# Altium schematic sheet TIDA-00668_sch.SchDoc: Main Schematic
size 431 x 279 mm; Date: Not shown in title block; ApprovedBy: Not shown in title block; CheckedBy: Not shown in title block; Author: Not shown in title block; CompanyName: Not shown in title block; DrawnBy: Gordon Varney; Engineer: Gordon Varney; Organization: Not shown in title block; Address1: Not shown in title block; Address2: Not shown in title block; Address3: Not shown in title block; Address4: Not shown in title block; DocumentNumber: 1; Revision: Use project parameter SCH_Rev; SheetNumber: 2; SheetTotal: 3; PageSetup: Record=PageOptions¦CenterHorizontal=True¦CenterVertical=True¦PrintScale=0.64¦XCorrection=1.00¦YCorrection=1.00¦PrintKind=0¦BorderSize=5000000¦LeftOffset=0¦BottomOffset=0¦Orientation=2¦PaperLength=1000¦PaperWidth=1000¦Scale=100¦PaperSource=15¦PrintQuality=600¦MediaType=1¦DitherType=10¦PrintScaleMode=1¦PaperKind=Letter
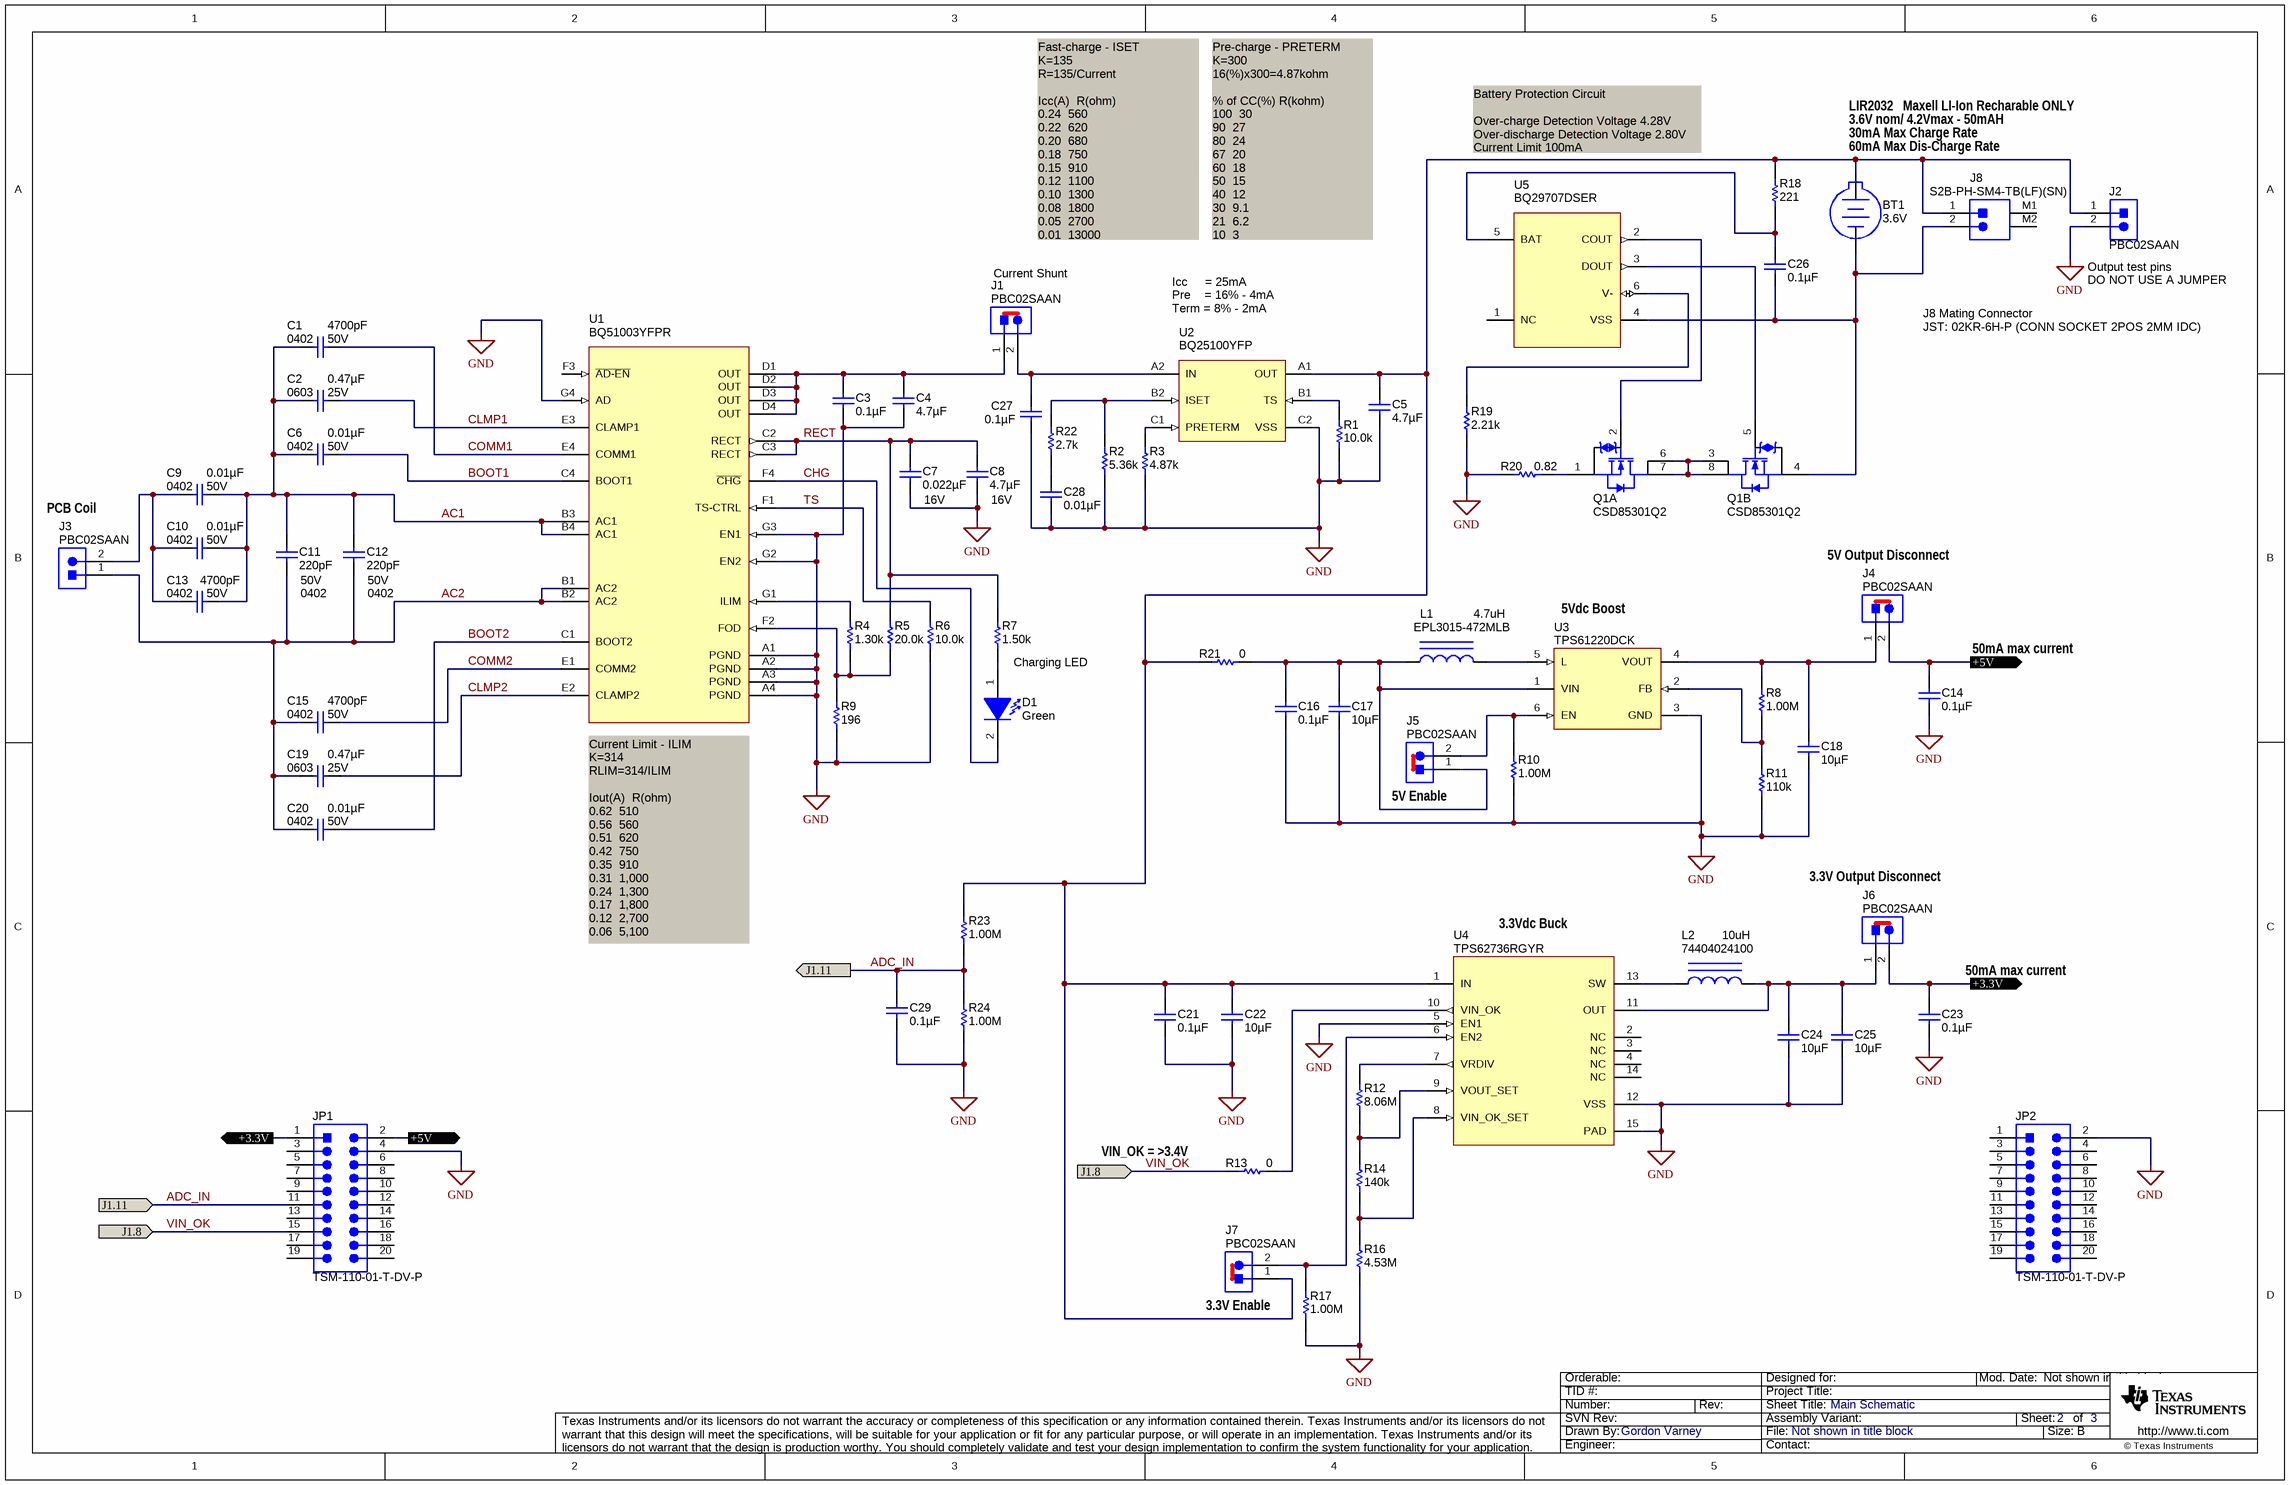
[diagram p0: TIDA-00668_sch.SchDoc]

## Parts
BT1  value 3.6V  [BAT_BS-7]  (hidden comment: BS-7)
C1  ValueDisplayed: 4700pF  Value2: 50V  [0402]  (hidden comment: C1005X8R1H472K)
C2  ValueDisplayed: 0.47µF  Value2: 25V  [0603]  (hidden comment: GRM188R71E474KA12D)
C3  ValueDisplayed: 0.1µF  [0402]  (hidden comment: GRM155R71A104KA01D)
C4  ValueDisplayed: 4.7µF  [0402]  (hidden comment: C1005X5R1A475K050BC)
C5  ValueDisplayed: 4.7µF  [0402]  (hidden comment: C1005X5R1A475K050BC)
C6  ValueDisplayed: 0.01µF  Value2: 50V  [0402]  (hidden comment: C0402C103J5RACTU)
C7  ValueDisplayed: 0.022µF  Value2: 16V  [0402]  (hidden comment: C1005X7R1C223K)
C8  ValueDisplayed: 4.7µF  Value2: 16V  [0603]  (hidden comment: GRM188R61C475KAAJ)
C9  ValueDisplayed: 0.01µF  Value2: 50V  [0402]  (hidden comment: C0402C103J5RACTU)
C10  ValueDisplayed: 0.01µF  Value2: 50V  [0402]  (hidden comment: C0402C103J5RACTU)
C11  ValueDisplayed: 220pF  Value2: 50V  [0402]  (hidden comment: GRM1555C1H221JA01D)
C12  ValueDisplayed: 220pF  Value2: 50V  [0402]  (hidden comment: GRM1555C1H221JA01D)
C13  ValueDisplayed: 4700pF  Value2: 50V  [0402]  (hidden comment: C1005X8R1H472K)
C14  ValueDisplayed: 0.1µF  [0402]  (hidden comment: GRM155R71A104KA01D)
C15  ValueDisplayed: 4700pF  Value2: 50V  [0402]  (hidden comment: C1005X8R1H472K)
C16  ValueDisplayed: 0.1µF  [0402]  (hidden comment: GRM155R71A104KA01D)
C17  ValueDisplayed: 10µF  [0603]  (hidden comment: C0603C106M9PACTU)
C18  ValueDisplayed: 10µF  [0603]  (hidden comment: C0603C106M9PACTU)
C19  ValueDisplayed: 0.47µF  Value2: 25V  [0603]  (hidden comment: GRM188R71E474KA12D)
C20  ValueDisplayed: 0.01µF  Value2: 50V  [0402]  (hidden comment: C0402C103J5RACTU)
C21  ValueDisplayed: 0.1µF  [0402]  (hidden comment: GRM155R71A104KA01D)
C22  ValueDisplayed: 10µF  [0603]  (hidden comment: C0603C106M9PACTU)
C23  ValueDisplayed: 0.1µF  [0402]  (hidden comment: GRM155R71A104KA01D)
C24  ValueDisplayed: 10µF  [0603]  (hidden comment: C0603C106M9PACTU)
C25  ValueDisplayed: 10µF  [0603]  (hidden comment: C0603C106M9PACTU)
C26  ValueDisplayed: 0.1µF  [0402]  (hidden comment: GRM155R71A104KA01D)
C27  ValueDisplayed: 0.1µF  [0402]  (hidden comment: GRM155R71A104KA01D)
C28  ValueDisplayed: 0.01µF  [0402]  (hidden comment: C0402C103J5RACTU)
C29  ValueDisplayed: 0.1µF  [0402]  (hidden comment: GRM155R71A104KA01D)
D1  value Green  [LED_LTST-C190]  (hidden comment: LTST-C190GKT)
J1  PBC02SAAN  [Sullins_PBC02SAAN]
J2  PBC02SAAN  [Sullins_PBC02SAAN]
J3  PBC02SAAN  [Sullins_PBC02SAAN]
J4  PBC02SAAN  [Sullins_PBC02SAAN]
J5  PBC02SAAN  [Sullins_PBC02SAAN]
J6  PBC02SAAN  [Sullins_PBC02SAAN]
J7  PBC02SAAN  [Sullins_PBC02SAAN]
J8  S2B-PH-SM4-TB(LF)(SN)  [JST_S2B-PH-SM4-TB]
JP1  TSM-110-01-T-DV-P  [CONN_TSM-110-01-T-DV-P]
JP2  TSM-110-01-T-DV-P  [CONN_TSM-110-01-T-DV-P]
L1  EPL3015-472MLB  value 4.7uH  [EPL3015]
L2  74404024100  value 10uH  [WE_LQS_252012]
Q1  CSD85301Q2  [DQK0006B]  (parts A,B of 2)
R1  ValueDisplayed: 10.0k  [0402]  (hidden comment: CRCW040210K0FKED)
R2  ValueDisplayed: 5.36k  [0402]  (hidden comment: CRCW04025K36FKED)
R3  ValueDisplayed: 4.87k  [0402]  (hidden comment: CRCW04024K87FKED)
R4  ValueDisplayed: 1.30k  [0402]  (hidden comment: CRCW04021K30FKED)
R5  ValueDisplayed: 20.0k  [0402]  (hidden comment: CRCW040220K0FKED)
R6  ValueDisplayed: 10.0k  [0402]  (hidden comment: CRCW040210K0FKED)
R7  ValueDisplayed: 1.50k  [0402]  (hidden comment: CRCW04021K50FKED)
R8  ValueDisplayed: 1.00M  [0402]  (hidden comment: CRCW04021M00FKED)
R9  ValueDisplayed: 196  [0402]  (hidden comment: CRCW0402196RFKED)
R10  ValueDisplayed: 1.00M  [0402]  (hidden comment: CRCW04021M00FKED)
R11  ValueDisplayed: 110k  [0402]  (hidden comment: CRCW0402110KFKED)
R12  ValueDisplayed: 8.06M  [0402]  (hidden comment: CRCW04028M06FKED)
R13  ValueDisplayed: 0  [0402]  (hidden comment: CRCW04020000Z0ED)
R14  ValueDisplayed: 140k  [0402]  (hidden comment: CRCW0402140KFKED)
R16  ValueDisplayed: 4.53M  [0402]  (hidden comment: CRCW04024M53FKED)
R17  ValueDisplayed: 1.00M  [0402]  (hidden comment: CRCW04021M00FKED)
R18  ValueDisplayed: 221  [0402]  (hidden comment: CRCW0402221RFKED)
R19  ValueDisplayed: 2.21k  [0402]  (hidden comment: CRCW04022K21FKED)
R20  ValueDisplayed: 0.82  [0402]  (hidden comment: ERJ-2BQFR82X)
R21  ValueDisplayed: 0  [0402]  (hidden comment: CRCW04020000Z0ED)
R22  ValueDisplayed: 2.7k  [0402]  (hidden comment: CRCW04022K70JNED)
R23  ValueDisplayed: 1.00M  [0402]  (hidden comment: CRCW04021M00FKED)
R24  ValueDisplayed: 1.00M  [0402]  (hidden comment: CRCW04021M00FKED)
U1  BQ51003YFPR  [YFP0028APAL]
U2  BQ25100YFP  [YFP0006AFAV]
U3  TPS61220DCK  [DCK0006A_N]
U4  TPS62736RGYR  [RGY0014A]
U5  BQ29707DSER  [DSE0006A]

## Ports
+3.3V, +5V, J1.8, J1.11

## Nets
GND: C3.2 C4.2 C5.2 C7.2 C8.2 C14.2 C16.2 C17.2 C18.2 C21.2 C22.2 C23.2 C24.2 C25.2 C27.2 C28.2 C29.2 J2.2 JP1.4 JP2.2 R1.1 R2.1 R3.1 R6.1 R9.1 R10.1 R11.1 R16.1 R17.1 R19.1 R20.1 R24.1 U1.A1(PGND) U1.A2(PGND) U1.A3(PGND) U1.A4(PGND) U1.G2(EN2) U1.G3(EN1) U1.G4(AD) U2.C2(VSS) U3.3(GND) U4.5(EN1) U4.12(VSS) U4.15(PAD)
+3.3V: C23.1 J6.2 JP1.1 ; port +3.3V
+5V: C14.1 J4.2 JP1.2 ; port +5V
AC1: C1.2 C2.2 C6.2 C9.1 C10.1 C11.1 C12.1 C13.1 U1.B3(AC1) U1.B4(AC1)
AC2: C11.2 C12.2 C15.2 C19.2 C20.2 J3.1 U1.B1(AC2) U1.B2(AC2)
ADC_IN: C29.1 JP1.11 R23.1 R24.2 ; port J1.11
BOOT1: C6.1 U1.C4(BOOT1)
BOOT2: C20.1 U1.C1(BOOT2)
CHG: D1.2(K) U1.F4(~{CHG})
CLMP1: C2.1 U1.E3(CLAMP1)
CLMP2: C19.1 U1.E2(CLAMP2)
COMM1: C1.1 U1.E4(COMM1)
COMM2: C15.1 U1.E1(COMM2)
RECT: C7.1 C8.1 R5.2 R7.2 U1.C2(RECT) U1.C3(RECT)
TS: R6.2 U1.F1(TS-CTRL)
VIN_OK: JP1.15 R13.1 ; port J1.8
NetBT1_1: BT1.1(+) C5.1 C21.1 C22.1 J2.1 J7.1 J8.1 R18.2 R21.1 R23.2 U2.A1(OUT) U4.1(IN)
NetBT1_2: BT1.2(-) C26.2 J8.2 Q1.4(S2) U5.4(VSS)
NetC3_1: C3.1 C4.1 J1.1 U1.D1(OUT) U1.D2(OUT) U1.D3(OUT) U1.D4(OUT)
NetC9_2: C9.2 C10.2 C13.2 J3.2
NetC16_1: C16.1 C17.1 J5.1 L1.1 R21.2 U3.1(VIN)
NetC18_1: C18.1 J4.1 R8.2 U3.4(VOUT)
NetC24_1: C24.1 C25.1 J6.1 L2.2 U4.11(OUT)
NetC26_1: C26.1 R18.1 U5.5(BAT)
NetC27_1: C27.1 J1.2 U2.A2(IN)
NetC28_1: C28.1 R22.1
NetD1_1: D1.1(A) R7.1
NetJ5_2: J5.2 R10.2 U3.6(EN)
NetJ7_2: J7.2 R17.2 U4.6(EN2)
NetL1_2: L1.2 U3.5(L)
NetL2_1: L2.1 U4.13(SW)
NetQ1_1: Q1.1(S1) R20.2
NetQ1_2: Q1.2(G1) U5.2(COUT)
NetQ1_3: Q1.3(D2) Q1.6(D1) Q1.7(D1) Q1.8(D2)
NetQ1_5: Q1.5(G2) U5.3(DOUT)
NetR1_2: R1.2 U2.B1(TS)
NetR2_2: R2.2 R22.2 U2.B2(ISET)
NetR3_2: R3.2 U2.C1(PRETERM)
NetR4_1: R4.1 R5.1 R9.2 U1.F2(FOD)
NetR4_2: R4.2 U1.G1(ILIM)
NetR8_1: R8.1 R11.2 U3.2(FB)
NetR12_1: R12.1 R14.2 U4.9(VOUT_SET)
NetR12_2: R12.2 U4.7(VRDIV)
NetR13_2: R13.2 U4.10(VIN_OK)
NetR14_1: R14.1 R16.2 U4.8(VIN_OK_SET)
NetR19_2: R19.2 U5.6(V-)

Not connected (* = marked no-connect by the designer): J8 M1 M2; JP1 3 5 6 7 8 9 10 12 13 14 16 17 18 19 20; JP2 1 3 4 5 6 7 8 9 10 11 12 13 14 15 16 17 18 19 20; U1 F3(~{AD-EN}); U4 2(NC) 3(NC) 4(NC) 14(NC); U5 1(NC)

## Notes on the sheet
- Battery Protection Circuit
  Over-charge Detection Voltage 4.28V
  Over-discharge Detection Voltage 2.80V
  Current Limit 100mA
- 3.6V nom/ 4.2Vmax - 50mAH
- LIR2032
- 60mA Max Dis-Charge Rate
- 30mA Max Charge Rate
- Maxell LI-Ion Recharable ONLY
- Current Shunt
- Fast-charge - ISET
  K=135
  R=135/Current
  Icc(A)		R(ohm)
  0.24		560
  0.22		620
  0.20		680
  0.18		750
  0.15		910
  0.12		1100
  0.10		1300
  0.08		1800
  0.05		2700
  0.01		13000
- Pre-charge - PRETERM
  K=300
  16(%)x300=4.87kohm
  % of CC(%)	R(kohm)
  100		30
  90		27
  80		24
  67		20
  60		18
  50		15
  40		12
  30		9.1
  21		6.2
  10		3
- (near J2) Output test pins
- (near J2) DO NOT USE A JUMPER
- Icc     = 25mA
  Pre    = 16% - 4mA
  Term = 8% - 2mA
- J8 Mating Connector
- JST: 02KR-6H-P (CONN SOCKET 2POS 2MM IDC)
- (near J3) PCB Coil
- 5V Output Disconnect
- (near U3) 5Vdc Boost
- (near R7) Charging LED
- (near C14) 50mA max current
- (near J5) 5V Enable
- 3.3V Output Disconnect
- (near U1) Current Limit - ILIM
  K=314
  RLIM=314/ILIM
  Iout(A)		R(ohm)
  0.62		510
  0.56		560
  0.51		620
  0.42		750
  0.35		910
  0.31		1,000
  0.24		1,300
  0.17		1,800
  0.12		2,700
  0.06		5,100
- (near U4) 3.3Vdc Buck
- (near C23) 50mA max current
- (near R13) VIN_OK = >3.4V
- 3.3V Enable

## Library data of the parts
BT1 = BS-7: Battery Holder, CR2032, Retainer clip, TH; Manufacturer: Memory Protection Devices; SymbolCreator: a0412235
C1 C13 C15 = C1005X8R1H472K: CAP, CERM, 4700 pF, 50 V, +/- 10%, X8R, 0402; Manufacturer: TDK; Polarized: N; CompType: Capacitor; Value: 4700pF; U/M: EA; Cap_F: 0.0000000047; Tolerance_%: 10; ESR_ohm: 0.0899; Value1: 0.0899 ohm; VDC_V: 50; TaMin_C: -55; TaMax_C: 150; AEC Category: Q200
C2 C19 = GRM188R71E474KA12D: CAP, CERM, 0.47 µF, 25 V, +/- 10%, X7R, 0603; Manufacturer: MuRata; Polarized: N; CompType: Capacitor; Value: 0.47uF; U/M: EA; Cap_F: 0.00000047; Tolerance_%: 10; Value1: Unknown; VDC_V: 25; TaMin_C: -55; TaMax_C: 125
C3 C14 C16 C21 C23 C26 C27 C29 = GRM155R71A104KA01D: CAP, CERM, 0.1uF, 10V, +/-10%, X7R, 0402; Manufacturer: MuRata; Polarized: N; CompType: Capacitor; U/M: EA; Cap_F: 0.0000001; Tolerance_%: 10; Value1: Unknown; TaMin_C: -55; TaMax_C: 125
C4 C5 = C1005X5R1A475K050BC: CAP, CERM, 4.7 µF, 10 V, +/- 10%, X5R, 0402; Manufacturer: TDK; Polarized: N; CompType: Capacitor; Value: 4.7uF; U/M: EA; Cap_F: 0.0000047; Tolerance_%: 10; Value1: Unknown; Value2: 10V; TaMin_C: -55; TaMax_C: 85
C6 C20 = C0402C103J5RACTU: CAP, CERM, 0.01 µF, 50 V, +/- 5%, X7R, 0402; Manufacturer: Kemet; Polarized: N; CompType: Capacitor; Value: 0.01uF; U/M: EA; Cap_F: 0.00000001; Tolerance_%: 5; Value1: Unknown; VDC_V: 50; TaMin_C: -55; TaMax_C: 125
C7 = C1005X7R1C223K: CAP, CERM, 0.022 µF, 16 V, +/- 10%, X7R, 0402; Manufacturer: TDK; Polarized: N; CompType: Capacitor; Value: 0.022uF; U/M: EA; Cap_F: 0.000000022; Tolerance_%: 10; ESR_ohm: 0.0419; Value1: 0.0419 ohm; VDC_V: 16; TaMin_C: -55; TaMax_C: 125
C8 = GRM188R61C475KAAJ: CAP, CERM, 4.7 µF, 16 V, +/- 10%, X5R, 0603; Manufacturer: MuRata; Polarized: N; CompType: Capacitor; Value: 4.7uF; U/M: EA; Cap_F: 0.0000047; Tolerance_%: 10; Value1: Unknown; VDC_V: 16; TaMin_C: -55; TaMax_C: 85
C9 C10 = C0402C103J5RACTU: CAP, CERM, 0.01 µF, 50 V, +/- 5%, X7R, 0402; Manufacturer: Kemet; Polarized: N; CompType: Capacitor; Value: 0.01uF; U/M: EA; Cap_F: 0.00000001; Tolerance_%: 5; Value1: Unknown; VDC_V: 50; TaMin_C: -55; TaMax_C: 125; AEC Category: Q200
C11 C12 = GRM1555C1H221JA01D: CAP, CERM, 220 pF, 50 V, +/- 5%, C0G/NP0, 0402; Manufacturer: MuRata; Polarized: N; CompType: Capacitor; Value: 220pF; U/M: EA; Cap_F: 0.00000000022; Tolerance_%: 5; Value1: Unknown; VDC_V: 50; TaMin_C: -55; TaMax_C: 125; AEC Category: Q200
C17 C18 C22 C24 C25 = C0603C106M9PACTU: CAP, CERM, 10 µF, 6.3 V, +/- 20%, X5R, 0603; Manufacturer: Kemet; Polarized: N; CompType: Capacitor; Value: 10uF; U/M: EA; Cap_F: 0.00001; Tolerance_%: 20; ESR_ohm: 0.004; Value1: 0.004 ohm; VDC_V: 6.3; Value2: 6.3V; IRMS_A: 8.9; TaMin_C: -55; TaMax_C: 85
C28 = C0402C103J5RACTU: CAP, CERM, 0.01 µF, 50 V, +/- 5%, X7R, 0402; Manufacturer: Kemet; Polarized: N; CompType: Capacitor; Value: 0.01uF; U/M: EA; Cap_F: 0.00000001; Tolerance_%: 5; Value1: Unknown; VDC_V: 50; Value2: 50V; TaMin_C: -55; TaMax_C: 125
D1 = LTST-C190GKT: LED, Green, SMD; Manufacturer: Lite-On; Vf_V: 2.1; Value2: 2.1V; Io_A: 0.02; Power_TotalModule: 0.1; Value1: 0.1W; U/M: EA
J1-J7 = PBC02SAAN: Header, 100mil, 2x1, Gold, TH; Manufacturer: Sullins Connector Solutions; SymbolCreator: a0412235; U/M: EA
J8 = S2B-PH-SM4-TB(LF)(SN): Header (shrouded), 2mm, 2x1, R/A, SMT; Manufacturer: JST Manufacturing; SymbolCreator: x0208326; U/M: EA
JP1 JP2 = TSM-110-01-T-DV-P: Header, 100mil, 10x2, Tin, SMT; Manufacturer: Samtec; SymbolCreator: a0412235; U/M: EA
L1 = EPL3015-472MLB: Inductor, Shielded, Ferrite, 4.7 µH, 1.2 A, 0.14 ohm, SMD; Manufacturer: Coilcraft; Ind_H: 4.7E-6; ValueDisplayed: 4.7µH; Imax_A: 1.2; Irms: 1.4A @ 40C rise; Isat: 1.2A @ 30% inductance drop; DCR_ohm: 0.14; Value2: 1.2A
L2 = 74404024100: Inductor, Wirewound, Ferrite, 10 µH, 0.47 A, 0.435 ohm, SMD; Manufacturer: Wurth Elektronik eiSos; Ind_H: 10.0E-6; ValueDisplayed: 10µH; Imax_A: 0.47; Irms: 0.47A @ 40C rise; Isat: 0.85A @ 30% inductance drop; DCR_ohm: 0.435; Value2: 0.47A
Q1 = CSD85301Q2: MOSFET, N-CH, 20 V, 6.7 A, SMD, 2.0x2.0, Height 0.8mm; Manufacturer: Texas Instruments; Alternate Manufacturer: None; SymbolCreator: a0411947; U/M: EA; ChType: N; Value: 20V; VdsMax_V: 20; Value1: 0.023 ohm; Rdson45_ohm: 0.023; Value2: 4.2 nC; QgTyp_nC: 4.2; Vgs_V: 10; IdsMax_A: 6.7
R1 R6 = CRCW040210K0FKED: RES, 10.0 k, 1%, 0.063 W, 0402; Manufacturer: Vishay-Dale; CompType: Resistor; Value: 10.0k; Res_ohm: 10000; Value_Code: 10k0; Tolerance_%: 1; Power_W: 0.063; Value2: 0.063W; VDC_V: 50; TempCo: 100 ppm/C; EIA_Code: E96; U/M: EA
R2 = CRCW04025K36FKED: RES, 5.36 k, 1%, 0.063 W, 0402; Manufacturer: Vishay-Dale; CompType: Resistor; Value: 5.36k; Res_ohm: 5360; Value_Code: 5k36; Tolerance_%: 1; Power_W: 0.063; Value2: 0.063W; VDC_V: 50; TempCo: 100 ppm/C; EIA_Code: E96; U/M: EA
R3 = CRCW04024K87FKED: RES, 4.87 k, 1%, 0.063 W, 0402; Manufacturer: Vishay-Dale; CompType: Resistor; Value: 4.87k; Res_ohm: 4870; Value_Code: 4k87; Tolerance_%: 1; Power_W: 0.063; Value2: 0.063W; VDC_V: 50; TempCo: 100 ppm/C; EIA_Code: E96; U/M: EA
R4 = CRCW04021K30FKED: RES, 1.30 k, 1%, 0.063 W, 0402; Manufacturer: Vishay-Dale; CompType: Resistor; Value: 1.30k; Res_ohm: 1300; Value_Code: 1k30; Tolerance_%: 1; Power_W: 0.063; Value2: 0.063W; VDC_V: 50; TempCo: 100 ppm/C; EIA_Code: E96; U/M: EA
R5 = CRCW040220K0FKED: RES, 20.0 k, 1%, 0.063 W, 0402; Manufacturer: Vishay-Dale; CompType: Resistor; Value: 20.0k; Res_ohm: 20000; Value_Code: 20k0; Tolerance_%: 1; Power_W: 0.063; Value2: 0.063W; VDC_V: 50; TempCo: 100 ppm/C; EIA_Code: E96; U/M: EA
R7 = CRCW04021K50FKED: RES, 1.50 k, 1%, 0.063 W, 0402; Manufacturer: Vishay-Dale; CompType: Resistor; Value: 1.50k; Res_ohm: 1500; Value_Code: 1k50; Tolerance_%: 1; Power_W: 0.063; Value2: 0.063W; VDC_V: 50; TempCo: 100 ppm/C; EIA_Code: E96; U/M: EA
R8 R10 R17 R23 R24 = CRCW04021M00FKED: RES, 1.00 M, 1%, 0.063 W, 0402; Manufacturer: Vishay-Dale; CompType: Resistor; Value: 1.00Meg; Res_ohm: 1000000; Value_Code: 1M00; Tolerance_%: 1; Power_W: 0.063; Value2: 0.063W; VDC_V: 50; TempCo: 100 ppm/C; EIA_Code: E96; U/M: EA
R9 = CRCW0402196RFKED: RES, 196, 1%, 0.063 W, 0402; Manufacturer: Vishay-Dale; CompType: Resistor; Value: 196; Value_Code: 196R; Tolerance_%: 1; Power_W: 0.063; Value2: 0.063W; VDC_V: 50; TempCo: 100 ppm/C; EIA_Code: E96; U/M: EA
R11 = CRCW0402110KFKED: RES, 110 k, 1%, 0.063 W, 0402; Manufacturer: Vishay-Dale; CompType: Resistor; Value: 110k; Res_ohm: 110000; Tolerance_%: 1; Power_W: 0.063; Value2: 0.063W; VDC_V: 50; TempCo: 100 ppm/C; EIA_Code: E96; U/M: EA
R12 = CRCW04028M06FKED: RES, 8.06 M, 1%, 0.063 W, 0402; Manufacturer: Vishay-Dale; CompType: Resistor; Value: 8.06Meg; Res_ohm: 8060000; Value_Code: 8M06; Tolerance_%: 1; Power_W: 0.063; Value2: 0.063W; VDC_V: 50; TempCo: 100 ppm/C; EIA_Code: E96; U/M: EA
R13 R21 = CRCW04020000Z0ED: RES, 0, 5%, 0.063 W, 0402; Manufacturer: Vishay-Dale; CompType: Resistor; Value: 0; Value_Code: 0000; Tolerance_%: 5; Power_W: 0.063; Value2: 0.063W; VDC_V: 50; TempCo: 200 ppm/C; EIA_Code: E24; U/M: EA
R14 = CRCW0402140KFKED: RES, 140 k, 1%, 0.063 W, 0402; Manufacturer: Vishay-Dale; CompType: Resistor; Value: 140k; Res_ohm: 140000; Tolerance_%: 1; Power_W: 0.063; Value2: 0.063W; VDC_V: 50; TempCo: 100 ppm/C; EIA_Code: E96; U/M: EA
R16 = CRCW04024M53FKED: RES, 4.53 M, 1%, 0.063 W, 0402; Manufacturer: Vishay-Dale; CompType: Resistor; Value: 4.53Meg; Res_ohm: 4530000; Value_Code: 4M53; Tolerance_%: 1; Power_W: 0.063; Value2: 0.063W; VDC_V: 50; TempCo: 100 ppm/C; EIA_Code: E96; U/M: EA
R18 = CRCW0402221RFKED: RES, 221, 1%, 0.063 W, 0402; Manufacturer: Vishay-Dale; CompType: Resistor; Value: 221; Value_Code: 221R; Tolerance_%: 1; Power_W: 0.063; Value2: 0.063W; VDC_V: 50; TempCo: 100 ppm/C; EIA_Code: E96; U/M: EA
R19 = CRCW04022K21FKED: RES, 2.21 k, 1%, 0.063 W, 0402; Manufacturer: Vishay-Dale; CompType: Resistor; Value: 2.21k; Res_ohm: 2210; Value_Code: 2k21; Tolerance_%: 1; Power_W: 0.063; Value2: 0.063W; VDC_V: 50; TempCo: 100 ppm/C; EIA_Code: E96; U/M: EA
R20 = ERJ-2BQFR82X: RES, 0.82, 1%, 0.125 W, 0402; Manufacturer: Panasonic; CompType: Resistor; Value: 0.82; Value_Code: R820; Tolerance_%: 1; Power_W: 0.125; Value2: 0.125W; TempCo: 250 ppm/C; EIA_Code: E96; U/M: EA
R22 = CRCW04022K70JNED: RES, 2.7 k, 5%, 0.063 W, 0402; Manufacturer: Vishay-Dale; CompType: Resistor; Value: 2.7k; Res_ohm: 2700; Value_Code: 2k70; Tolerance_%: 5; Power_W: 0.063; Value2: 0.063W; VDC_V: 50; TempCo: 200 ppm/C; EIA_Code: E24; U/M: EA
U1 = BQ51003YFPR: Highly Integrated Wireless Receiver Qi (WPC v1.1) Compliant Power Supply, YFP0028APAL; Alternate PartNumber: BQ51003YFPT; Manufacturer: Texas Instruments; SymbolCreator: Altium; CompType: IC; U/M: EA
U2 = BQ25100YFP: 400 mA Single-Input, Single Cell Li-Ion Battery Chargers, YFP0006AFAV; Manufacturer: Texas Instruments; SymbolCreator: x0208326; CompType: IC; U/M: EA
U3 = TPS61220DCK: LOW INPUT VOLTAGE STEP-UP CONVERTER IN 6 PIN SC-70 PACKAGE, DCK0006A; Manufacturer: Texas Instruments; SymbolCreator: a0799628; CompType: IC; U/M: EA
U4 = TPS62736RGYR: Programmable Output Voltage Ultra-Low Power Buck Converter With Up to 50 mA Output Current, RGY0014A; Alternate PartNumber: TPS62736RGYT; Manufacturer: Texas Instruments; SymbolCreator: Altium; CompType: IC; U/M: EA
U5 = BQ29700DSER: Cost-Effective Voltage and Current Protection Integrated Circuit for Single-Cell Li-Ion/Li-Polymer Batteries, DSE0006A; Alternate PartNumber: BQ29707DSET; Manufacturer: Texas Instruments; SymbolCreator: a0412235; CompType: IC; U/M: EA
